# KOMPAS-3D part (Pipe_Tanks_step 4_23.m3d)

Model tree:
1. X Axis
2. Y Axis
3. Z Axis  (labels: Valve Dy 50; Pipe Dn 20; Bend 90 Dn 20)
     Òîëùèíà ñòåíêè 1 = 1

Referenced files in C:\Documents and Settings\kashirsky\Мои документы\Camtasia Studio\Pipelines3D\Tanks\: Tanks_step 4.a3d
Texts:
  Pipe Dn 20
  Steel ASTM A295
  Three Point Plane
  Plane at Angle
  Line and Point Plane
  Axis through Two Vertices
  Axis of Feature
  Axis of Conical Surface
  Axis through Edge
  Trim by Surface
  Trim by Sketch
  Feature with No History
  Intersection Axis of Two Planes
  Two Line Plane
  Line and Face Plane
  Bend by line
  Hole in sheet body
  Cut in sheet body
  Point in CM
  Linear Dimension from Line to Point
  Surface Finish Symbol
  Geometric Tolerance Symbol
  Leader #1
  Leader #2
  Leader #3
  Shape Deviations and Datum
  Node point number
  Mark of coordination axis
  Node point designation
  Mark/Reference designation with leader
  Mark/reference designation on line
  Mark/Reference designation without leader
  Valve Dy 50
  Bend 90 Dn 20
  Plane of section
